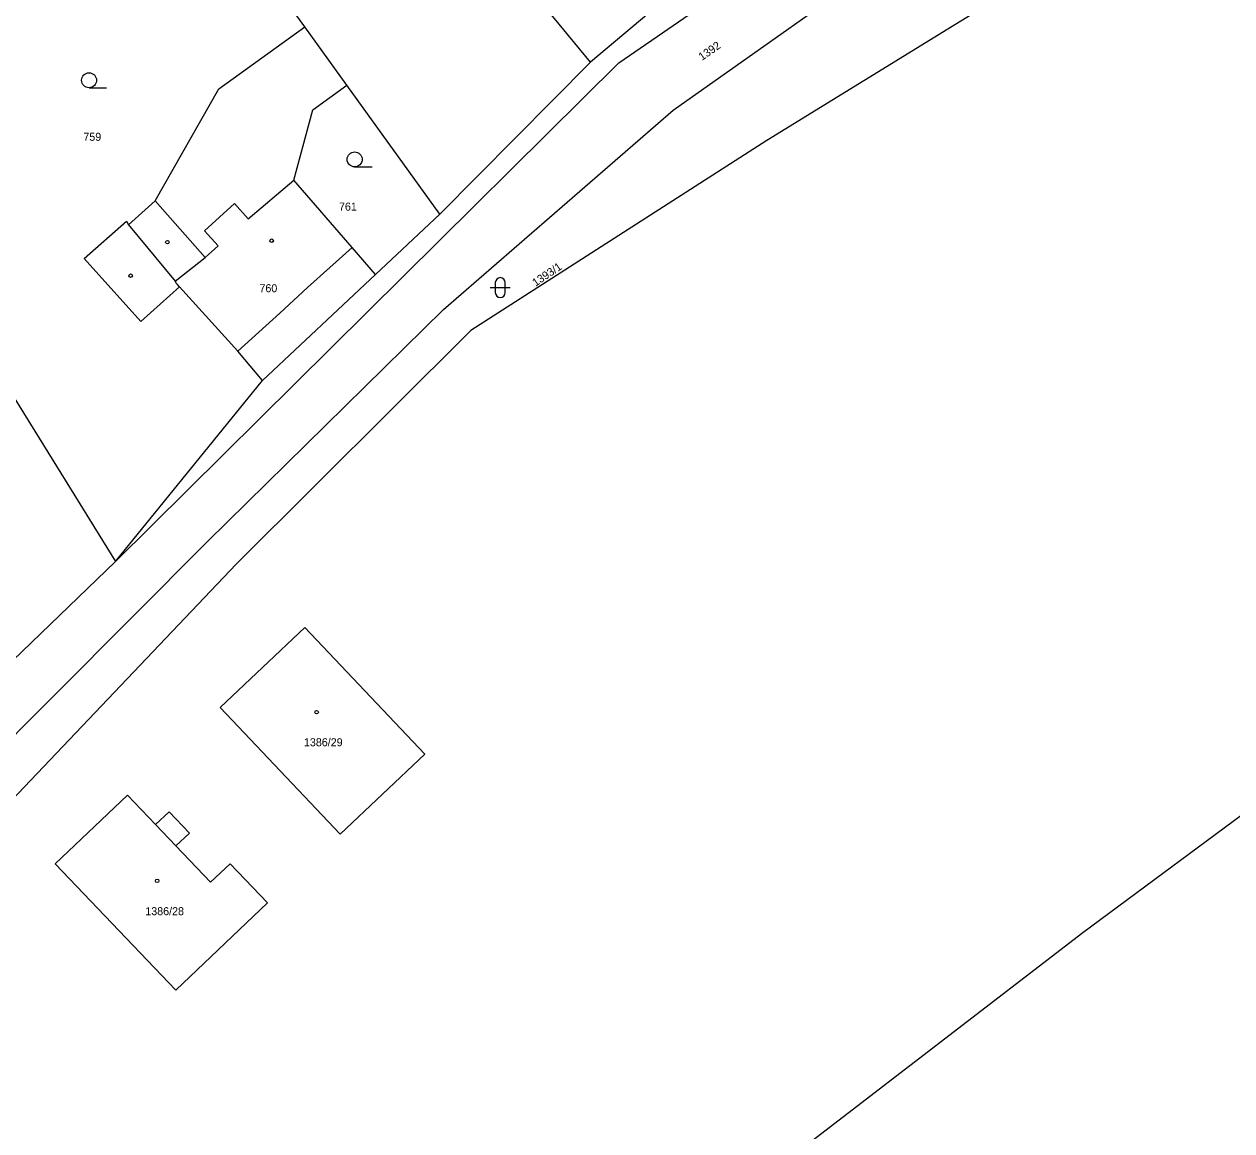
# Model space of a CAD drawing. Extents: x -719706 to -718922, y -950351 to -949651.
# Drawn here: x -719308.7 to -719188, y -950110.8 to -950000.1 of the extents above; entities that cross this region are included whole.
import ezdxf

# ---------------------------------------------------------------- set-up
doc = ezdxf.new("R2010")
doc.units = 0
doc.layers.add('Doplňující texty', color=7, linetype='Continuous')

msp = doc.modelspace()

# ---------------------------------------------------------------- linework, layer by layer
at = {"layer": 'Doplňující texty'}
for p, q in [((-719252.13, -950003.93), (-719290.52, -949956.95)), ((-719280.68, -950000.37), (-719303.75, -949968.42)), ((-719276.48, -950006.21), (-719280.68, -950000.37)), ((-719252.13, -950003.93), (-719267.17, -950019.1)), ((-719302.24, -950006.48), (-719300.49, -950006.48)), ((-719267.17, -950019.1), (-719276.48, -950006.21)), ((-719275.69, -950014.39), (-719273.94, -950014.39)), ((-719286.34, -950019.58), (-719281.78, -950015.7)), ((-719295.64, -950017.78), (-719290.64, -950023.46)), ((-719290.7, -950020.77), (-719287.71, -950018.06)), ((-719287.71, -950018.06), (-719286.34, -950019.58)), ((-719273.61, -950025.14), (-719267.17, -950019.1)), ((-719298.31, -950020.19), (-719293.64, -950025.81)), ((-719289.33, -950022.28), (-719290.7, -950020.77)), ((-719290.64, -950023.46), (-719289.33, -950022.28)), ((-719275.93, -950022.46), (-719280.4, -950026.46)), ((-719293.64, -950025.81), (-719290.64, -950023.46)), ((-719284.9, -950035.73), (-719273.61, -950025.14)), ((-719293.49, -950026.04), (-719293.64, -950025.81)), ((-719293.42, -950026.12), (-719293.49, -950026.04)), ((-719293.19, -950026.38), (-719293.42, -950026.12)), ((-719280.4, -950026.46), (-719283.17, -950029)), ((-719262.13, -950026.46), (-719260.13, -950026.46)), ((-719261.63, -950025.96), (-719261.63, -950026.96)), ((-719260.63, -950026.96), (-719260.63, -950025.96)), ((-719283.17, -950029), (-719287.38, -950032.81)), ((-719312.79, -950032.57), (-719299.59, -950053.84)), ((-719299.59, -950053.84), (-719284.9, -950035.73)), ((-719295.59, -950080.14), (-719293.56, -950082.28))]:
    msp.add_line(p, q, dxfattribs=at)
for points in [[(-719331.83, -950096.3), (-719313.31, -950074.81), (-719290.41, -950051.84), (-719266.82, -950028.65), (-719243.86, -950008.71), (-719196.45, -949975.23)], [(-719186, -949981.9), (-719234.5, -950011.76), (-719264.08, -950030.76), (-719287.51, -950054.06), (-719331.24, -950100.07)], [(-719234.08, -949989.31), (-719236.28, -949990.6), (-719252.13, -950003.93)], [(-719299.59, -950053.84), (-719249.29, -950004), (-719232.45, -949992.38)], [(-719284.9, -950035.73), (-719287.38, -950032.81), (-719293.19, -950026.38), (-719297.08, -950029.86), (-719302.74, -950023.53), (-719298.5, -950019.8), (-719298.31, -950020.19), (-719295.64, -950017.78), (-719289.28, -950006.57), (-719280.68, -950000.37)], [(-719273.61, -950025.14), (-719275.93, -950022.46), (-719281.78, -950015.7), (-719279.88, -950008.67), (-719276.48, -950006.21)], [(-719126.38, -950037.81), (-719154.2, -950057.28), (-719184.27, -950077.15), (-719202.89, -950090.97), (-719243.68, -950122.31), (-719293.03, -950169.31), (-719360.2, -950220.1), (-719387.28, -950232.05), (-719421.72, -950250.15), (-719452.59, -950265.64), (-719506.49, -950290.59), (-719587.31, -950333.84), (-719619.07, -950350.8)], [(-719299.59, -950053.84), (-719327.59, -950080.79), (-719329.5, -950081.67), (-719331.97, -950081.56), (-719334.55, -950080.07), (-719335.69, -950077.94)], [(-719277.14, -950081.1), (-719289.14, -950068.44), (-719280.68, -950060.43), (-719268.69, -950073.09), (-719277.14, -950081.1)], [(-719293.58, -950096.7), (-719305.62, -950084.06), (-719298.39, -950077.2), (-719295.59, -950080.14), (-719294.25, -950078.87), (-719292.2, -950080.99), (-719293.56, -950082.28), (-719290.1, -950085.91), (-719288.15, -950084.07), (-719284.4, -950087.98), (-719293.58, -950096.7)]]:
    msp.add_lwpolyline(points, dxfattribs=at)
for centre, radius in [((-719302.24, -950005.73), 0.75), ((-719275.69, -950013.64), 0.75), ((-719294.41, -950021.92), 0.175), ((-719283.98, -950021.77), 0.175), ((-719298.09, -950025.27), 0.175), ((-719279.49, -950068.9), 0.175), ((-719295.44, -950085.76), 0.175)]:
    msp.add_circle(centre, radius, dxfattribs=at)
for centre, start, end in [((-719261.13, -950025.96), 0, 180), ((-719261.13, -950026.96), 180, 359.9879)]:
    msp.add_arc(centre, 0.5, start, end, dxfattribs=at)

# ---------------------------------------------------------------- texts
for s, rotation, p in [('1392', 35, (-719240.97, -950003.8)), ('1393/1', 34, (-719257.61, -950026.38))]:
    msp.add_text(s, height=0.8, rotation=rotation, dxfattribs=at).set_placement(p)
for s, p in [('759', (-719302.81, -950011.78)), ('761', (-719277.26, -950018.76)), ('760', (-719285.21, -950026.92)), ('1386/29', (-719280.76, -950072.31)), ('1386/28', (-719296.62, -950089.2))]:
    msp.add_text(s, height=0.8, dxfattribs=at).set_placement(p)

doc.saveas('drawing.dxf')
